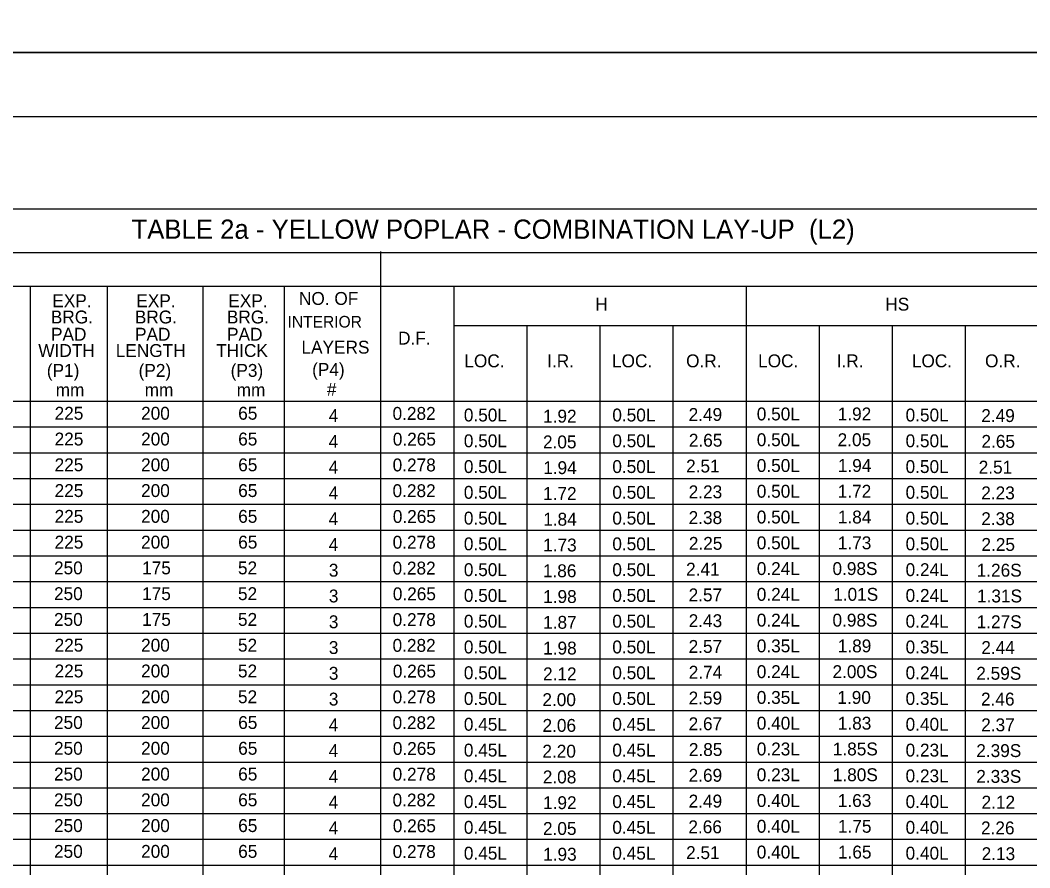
# Model space of a CAD drawing. Extents: x -5022 to -159, y 1126 to 7226.
# Drawn here: x -4362.8 to -4127.7, y 3906 to 4103.3 of the extents above; entities that cross this region are included whole.
import ezdxf

# ---------------------------------------------------------------- set-up
doc = ezdxf.new("R2010")
doc.units = 0
for name, color, linetype in [('2', 7, 'Continuous'), ('3', 7, 'Continuous'), ('PLT-BNDY', 7, 'Continuous')]:
    doc.layers.add(name, color=color, linetype=linetype)

msp = doc.modelspace()

# ---------------------------------------------------------------- linework, layer by layer
at = {"layer": '2'}
msp.add_line((-3855.13, 4080.81), (-4641.13, 4080.81), dxfattribs=at)
at = {"layer": '3'}
for p, q in [((-4601.11, 4059.4), (-3886.2, 4059.4)), ((-4600.86, 4049.23), (-3886.2, 4049.23)), ((-4278.85, 4049.48), (-4278.85, 3708.59)), ((-4601.11, 4041.41), (-3886.2, 4041.41)), ((-4360.48, 4041.41), (-4360.48, 3708.59)), ((-4342.55, 4041.41), (-4342.55, 3708.59)), ((-4320.24, 4041.41), (-4320.24, 3708.59)), ((-4301.29, 4041.41), (-4301.29, 3708.59)), ((-4261.83, 4041.41), (-4261.83, 3708.59)), ((-4193.74, 4041.41), (-4193.74, 3708.59)), ((-4261.83, 4032.2), (-3886.2, 4032.2)), ((-4244.8, 4032.2), (-4244.8, 3708.59)), ((-4227.78, 4032.2), (-4227.78, 3708.59)), ((-4227.78, 4032.2), (-4227.78, 3708.59)), ((-4210.76, 4032.2), (-4210.76, 3708.59)), ((-4193.75, 4032.2), (-4193.75, 3708.59)), ((-4176.73, 4032.2), (-4176.73, 3708.59)), ((-4159.71, 4032.2), (-4159.71, 3708.59)), ((-4159.7, 4032.2), (-4159.7, 3708.59)), ((-4142.69, 4032.2), (-4142.69, 3708.59)), ((-4601.11, 4014.6), (-3886.2, 4014.6)), ((-4583.63, 4008.6), (-3886.2, 4008.6)), ((-4583.63, 4002.6), (-3886.2, 4002.6)), ((-4601.11, 3996.6), (-3886.2, 3996.6)), ((-4583.63, 3990.59), (-3886.2, 3990.6)), ((-4583.63, 3984.59), (-3886.2, 3984.6)), ((-4601.11, 3978.59), (-3886.2, 3978.6)), ((-4583.63, 3972.59), (-3886.2, 3972.6)), ((-4583.63, 3966.6), (-3886.2, 3966.6)), ((-4601.11, 3960.6), (-3886.2, 3960.6)), ((-4583.63, 3954.59), (-3886.2, 3954.6)), ((-4583.63, 3948.59), (-3886.2, 3948.6)), ((-4601.11, 3942.59), (-3886.2, 3942.6)), ((-4583.63, 3936.59), (-3886.2, 3936.6)), ((-4583.63, 3930.59), (-3886.2, 3930.59)), ((-4601.11, 3924.59), (-3886.2, 3924.59)), ((-4583.63, 3918.59), (-3886.2, 3918.59)), ((-4583.63, 3912.59), (-3886.2, 3912.6)), ((-4601.11, 3906.59), (-3886.2, 3906.59))]:
    msp.add_line(p, q, dxfattribs=at)
at = {"layer": 'PLT-BNDY'}
for points in [[(-4681.13, 4689.81), (-3840.13, 4689.81), (-3840.13, 4095.81), (-4681.13, 4095.81)], [(-4681.13, 4095.81), (-3840.13, 4095.81), (-3840.13, 3501.81), (-4681.13, 3501.81)]]:
    msp.add_lwpolyline(points, close=True, dxfattribs=at)

# ---------------------------------------------------------------- texts
at = {"layer": '2'}
for s, height, p in [('TABLE 2a - YELLOW POPLAR - COMBINATION LAY-UP  (L2)', 4.4793, (-4336.86, 4052.41)), ('EXP.', 3, (-4355.31, 4036.49)), ('EXP.', 3, (-4335.74, 4036.49)), ('EXP.', 3, (-4314.31, 4036.49)), ('NO. OF', 3, (-4297.87, 4037.02)), ('H', 3, (-4228.86, 4035.69)), ('HS', 3, (-4161.31, 4035.69)), ('BRG.', 3, (-4355.65, 4032.7)), ('BRG.', 3, (-4336.08, 4032.7)), ('BRG.', 3, (-4314.65, 4032.7)), ('INTERIOR', 2.708, (-4300.52, 4031.75)), ('PAD', 3, (-4355.61, 4028.69)), ('PAD', 3, (-4336.04, 4028.69)), ('PAD', 3, (-4314.61, 4028.69)), ('D.F.', 3, (-4274.78, 4027.78)), ('WIDTH', 3, (-4358.57, 4024.9)), ('LENGTH', 3, (-4340.53, 4024.9)), ('THICK', 3, (-4317.14, 4024.9)), ('LAYERS', 3, (-4297.28, 4025.68)), ('LOC.', 3, (-4259.35, 4022.49)), ('I.R.', 3, (-4240.06, 4022.49)), ('LOC.', 3, (-4224.97, 4022.49)), ('O.R.', 3, (-4207.71, 4022.49)), ('LOC.', 3, (-4190.94, 4022.49)), ('I.R.', 3, (-4172.63, 4022.49)), ('LOC.', 3, (-4155.14, 4022.49)), ('O.R.', 3, (-4138.09, 4022.49)), ('(P1)', 3, (-4356.58, 4020.27)), ('(P2)', 3, (-4335.21, 4020.27)), ('(P3)', 3, (-4313.78, 4020.27)), ('(P4)', 3, (-4294.8, 4020.49)), ('#', 3, (-4291.36, 4015.85)), ('mm', 3, (-4354.52, 4015.74)), ('mm', 3, (-4333.8, 4015.74)), ('mm', 3, (-4312.37, 4015.74)), ('225', 3, (-4354.77, 4010.29)), ('200', 3, (-4334.63, 4010.29)), ('65', 3, (-4312.02, 4010.29)), ('4', 3, (-4290.94, 4009.75)), ('0.282', 3, (-4276.07, 4010.26)), ('0.50L', 3, (-4259.47, 4009.88)), ('1.92', 3, (-4241.02, 4009.62)), ('0.50L', 3, (-4224.89, 4009.88)), ('2.49', 3, (-4207.12, 4010.01)), ('0.50L', 3, (-4191.25, 4010.13)), ('1.92', 3, (-4172.4, 4010.13)), ('0.50L', 3, (-4156.59, 4009.88)), ('2.49', 3, (-4138.97, 4009.75)), ('225', 3, (-4354.77, 4004.29)), ('200', 3, (-4334.63, 4004.29)), ('65', 3, (-4312.02, 4004.29)), ('4', 3, (-4290.94, 4003.75)), ('0.265', 3, (-4276.01, 4004.26)), ('0.50L', 3, (-4259.47, 4003.88)), ('2.05', 3, (-4241.04, 4003.62)), ('0.50L', 3, (-4224.89, 4003.88)), ('2.65', 3, (-4207.07, 4004.01)), ('0.50L', 3, (-4191.25, 4004.13)), ('2.05', 3, (-4172.42, 4004.13)), ('0.50L', 3, (-4156.59, 4003.88)), ('2.65', 3, (-4138.93, 4003.75)), ('225', 3, (-4354.77, 3998.29)), ('200', 3, (-4334.63, 3998.29)), ('65', 3, (-4312.02, 3998.29)), ('4', 3, (-4290.94, 3997.75)), ('0.278', 3, (-4276.05, 3998.26)), ('0.50L', 3, (-4259.47, 3997.88)), ('1.94', 3, (-4240.99, 3997.62)), ('0.50L', 3, (-4224.89, 3997.88)), ('2.51', 3, (-4207.71, 3998)), ('0.50L', 3, (-4191.25, 3998.13)), ('1.94', 3, (-4172.37, 3998.13)), ('0.50L', 3, (-4156.59, 3997.88)), ('2.51', 3, (-4139.57, 3997.75)), ('225', 3, (-4354.77, 3992.29)), ('200', 3, (-4334.63, 3992.29)), ('65', 3, (-4312.02, 3992.29)), ('4', 3, (-4290.94, 3991.75)), ('0.282', 3, (-4276.07, 3992.26)), ('0.50L', 3, (-4259.47, 3991.88)), ('0.50L', 3, (-4224.89, 3991.88)), ('2.23', 3, (-4207.11, 3992)), ('0.50L', 3, (-4191.25, 3992.13)), ('1.72', 3, (-4172.4, 3992.13)), ('0.50L', 3, (-4156.59, 3991.88)), ('2.23', 3, (-4138.97, 3991.75)), ('1.72', 3, (-4241.02, 3991.62)), ('225', 3, (-4354.77, 3986.29)), ('200', 3, (-4334.63, 3986.29)), ('65', 3, (-4312.02, 3986.29)), ('4', 3, (-4290.94, 3985.75)), ('0.265', 3, (-4276.01, 3986.26)), ('0.50L', 3, (-4259.47, 3985.88)), ('1.84', 3, (-4240.99, 3985.62)), ('0.50L', 3, (-4224.89, 3985.88)), ('2.38', 3, (-4207.12, 3986)), ('0.50L', 3, (-4191.25, 3986.13)), ('1.84', 3, (-4172.37, 3986.13)), ('0.50L', 3, (-4156.59, 3985.88)), ('2.38', 3, (-4138.97, 3985.75)), ('225', 3, (-4354.77, 3980.29)), ('200', 3, (-4334.63, 3980.29)), ('65', 3, (-4312.02, 3980.29)), ('0.278', 3, (-4276.05, 3980.26)), ('2.25', 3, (-4207.07, 3980)), ('0.50L', 3, (-4191.25, 3980.13)), ('1.73', 3, (-4172.38, 3980.13)), ('4', 3, (-4290.94, 3979.75)), ('0.50L', 3, (-4259.47, 3979.88)), ('1.73', 3, (-4241, 3979.62)), ('0.50L', 3, (-4224.89, 3979.88)), ('0.50L', 3, (-4156.59, 3979.88)), ('2.25', 3, (-4138.93, 3979.75)), ('250', 3, (-4354.91, 3974.29)), ('175', 3, (-4334.39, 3974.29)), ('52', 3, (-4312.07, 3974.29)), ('3', 3, (-4290.91, 3973.75)), ('0.282', 3, (-4276.07, 3974.25)), ('0.50L', 3, (-4259.47, 3973.88)), ('1.86', 3, (-4241.06, 3973.62)), ('0.50L', 3, (-4224.89, 3973.88)), ('2.41', 3, (-4207.71, 3974)), ('0.24L', 3, (-4191.25, 3974.13)), ('0.98S', 3, (-4173.62, 3974.13)), ('0.24L', 3, (-4156.59, 3973.88)), ('1.26S', 3, (-4140.04, 3973.75)), ('250', 3, (-4354.91, 3968.29)), ('175', 3, (-4334.39, 3968.29)), ('52', 3, (-4312.07, 3968.29)), ('0.265', 3, (-4276.01, 3968.25)), ('3', 3, (-4290.91, 3967.75)), ('0.50L', 3, (-4259.47, 3967.88)), ('1.98', 3, (-4241, 3967.62)), ('0.50L', 3, (-4224.89, 3967.88)), ('2.57', 3, (-4207.12, 3968)), ('0.24L', 3, (-4191.25, 3968.13)), ('1.01S', 3, (-4173.45, 3968.13)), ('0.24L', 3, (-4156.59, 3967.88)), ('1.31S', 3, (-4139.96, 3967.75)), ('250', 3, (-4354.91, 3962.29)), ('175', 3, (-4334.39, 3962.29)), ('52', 3, (-4312.07, 3962.29)), ('3', 3, (-4290.91, 3961.75)), ('0.278', 3, (-4276.05, 3962.25)), ('0.50L', 3, (-4259.47, 3961.88)), ('1.87', 3, (-4241, 3961.62)), ('0.50L', 3, (-4224.89, 3961.88)), ('2.43', 3, (-4207.11, 3962)), ('0.24L', 3, (-4191.25, 3962.13)), ('0.98S', 3, (-4173.62, 3962.13)), ('0.24L', 3, (-4156.59, 3961.88)), ('1.27S', 3, (-4140.04, 3961.75)), ('225', 3, (-4354.77, 3956.29)), ('200', 3, (-4334.63, 3956.29)), ('52', 3, (-4312.07, 3956.29)), ('3', 3, (-4290.91, 3955.75)), ('0.282', 3, (-4276.07, 3956.25)), ('0.50L', 3, (-4259.47, 3955.88)), ('1.98', 3, (-4241, 3955.62)), ('0.50L', 3, (-4224.89, 3955.88)), ('2.57', 3, (-4207.12, 3956)), ('0.35L', 3, (-4191.25, 3956.13)), ('1.89', 3, (-4172.38, 3956.13)), ('0.35L', 3, (-4156.59, 3955.88)), ('2.44', 3, (-4138.96, 3955.75)), ('225', 3, (-4354.77, 3950.29)), ('200', 3, (-4334.63, 3950.29)), ('52', 3, (-4312.07, 3950.29)), ('3', 3, (-4290.91, 3949.75)), ('0.265', 3, (-4276.01, 3950.26)), ('0.50L', 3, (-4259.47, 3949.88)), ('2.12', 3, (-4241.02, 3949.62)), ('0.50L', 3, (-4224.89, 3949.88)), ('2.74', 3, (-4207.1, 3950)), ('0.24L', 3, (-4191.25, 3950.13)), ('2.00S', 3, (-4173.62, 3950.13)), ('0.24L', 3, (-4156.59, 3949.88)), ('2.59S', 3, (-4140.13, 3949.75)), ('225', 3, (-4354.77, 3944.29)), ('200', 3, (-4334.63, 3944.29)), ('52', 3, (-4312.07, 3944.29)), ('3', 3, (-4290.91, 3943.75)), ('0.278', 3, (-4276.05, 3944.25)), ('0.50L', 3, (-4259.47, 3943.88)), ('2.00', 3, (-4241.18, 3943.62)), ('0.50L', 3, (-4224.89, 3943.88)), ('2.59', 3, (-4207.12, 3944)), ('0.35L', 3, (-4191.25, 3944.13)), ('1.90', 3, (-4172.48, 3944.13)), ('0.35L', 3, (-4156.59, 3943.88)), ('2.46', 3, (-4139.03, 3943.75)), ('250', 3, (-4354.91, 3938.29)), ('200', 3, (-4334.63, 3938.29)), ('65', 3, (-4312.02, 3938.29)), ('4', 3, (-4290.94, 3937.75)), ('0.282', 3, (-4276.07, 3938.25)), ('0.45L', 3, (-4259.47, 3937.88)), ('2.06', 3, (-4241.14, 3937.62)), ('0.45L', 3, (-4224.89, 3937.88)), ('2.67', 3, (-4207.12, 3938)), ('0.40L', 3, (-4191.25, 3938.13)), ('1.83', 3, (-4172.38, 3938.13)), ('0.40L', 3, (-4156.59, 3937.88)), ('2.37', 3, (-4138.98, 3937.75)), ('250', 3, (-4354.91, 3932.29)), ('200', 3, (-4334.63, 3932.29)), ('65', 3, (-4312.02, 3932.29)), ('4', 3, (-4290.94, 3931.75)), ('0.265', 3, (-4276.01, 3932.25)), ('0.45L', 3, (-4259.47, 3931.87)), ('2.20', 3, (-4241.18, 3931.62)), ('0.45L', 3, (-4224.89, 3931.87)), ('2.85', 3, (-4207.07, 3932)), ('0.23L', 3, (-4191.25, 3932.13)), ('1.85S', 3, (-4173.54, 3932.13)), ('0.23L', 3, (-4156.59, 3931.87)), ('2.39S', 3, (-4140.13, 3931.75)), ('250', 3, (-4354.91, 3926.29)), ('200', 3, (-4334.63, 3926.29)), ('65', 3, (-4312.02, 3926.29)), ('0.278', 3, (-4276.05, 3926.26)), ('0.45L', 3, (-4259.47, 3925.88)), ('0.45L', 3, (-4224.89, 3925.88)), ('2.69', 3, (-4207.12, 3926)), ('0.23L', 3, (-4191.25, 3926.13)), ('1.80S', 3, (-4173.54, 3926.13)), ('0.23L', 3, (-4156.59, 3925.88)), ('4', 3, (-4290.94, 3925.75)), ('2.08', 3, (-4241.08, 3925.62)), ('2.33S', 3, (-4140.13, 3925.75)), ('250', 3, (-4354.91, 3920.29)), ('200', 3, (-4334.63, 3920.29)), ('65', 3, (-4312.02, 3920.29)), ('4', 3, (-4290.94, 3919.75)), ('0.282', 3, (-4276.07, 3920.25)), ('0.45L', 3, (-4259.47, 3919.88)), ('1.92', 3, (-4241.02, 3919.62)), ('0.45L', 3, (-4224.89, 3919.88)), ('2.49', 3, (-4207.12, 3920)), ('0.40L', 3, (-4191.25, 3920.13)), ('1.63', 3, (-4172.38, 3920.13)), ('0.40L', 3, (-4156.59, 3919.88)), ('2.12', 3, (-4138.9, 3919.75)), ('250', 3, (-4354.91, 3914.29)), ('200', 3, (-4334.63, 3914.29)), ('65', 3, (-4312.02, 3914.29)), ('0.265', 3, (-4276.01, 3914.25)), ('0.40L', 3, (-4191.25, 3914.13)), ('1.75', 3, (-4172.34, 3914.13)), ('4', 3, (-4290.94, 3913.75)), ('0.45L', 3, (-4259.47, 3913.88)), ('2.05', 3, (-4241.04, 3913.62)), ('0.45L', 3, (-4224.89, 3913.88)), ('2.66', 3, (-4207.18, 3914)), ('0.40L', 3, (-4156.59, 3913.88)), ('2.26', 3, (-4139.03, 3913.75)), ('250', 3, (-4354.91, 3908.29)), ('200', 3, (-4334.63, 3908.29)), ('65', 3, (-4312.02, 3908.29)), ('4', 3, (-4290.94, 3907.75)), ('0.278', 3, (-4276.05, 3908.25)), ('0.45L', 3, (-4259.47, 3907.87)), ('1.93', 3, (-4241, 3907.62)), ('0.45L', 3, (-4224.89, 3907.87)), ('2.51', 3, (-4207.71, 3908)), ('0.40L', 3, (-4191.25, 3908.13)), ('1.65', 3, (-4172.34, 3908.13)), ('0.40L', 3, (-4156.59, 3907.87)), ('2.13', 3, (-4138.88, 3907.75))]:
    msp.add_text(s, height=height, dxfattribs=at).set_placement(p)

doc.saveas('drawing.dxf')
